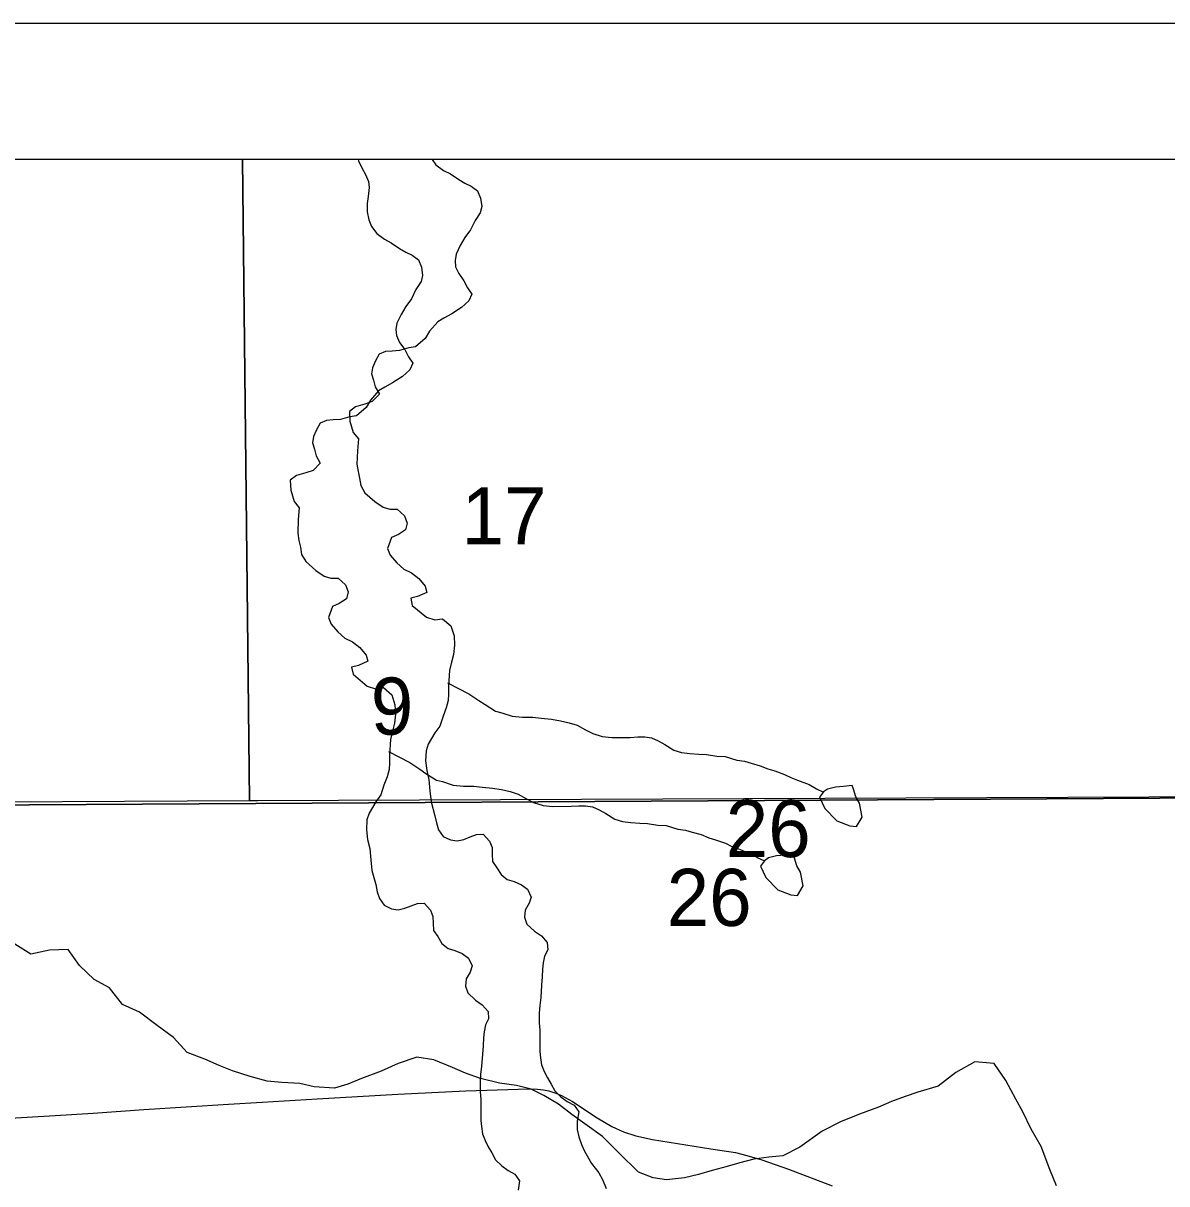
# Model space of a CAD drawing. Extents: x -21.1 to 50.3, y -4.9 to 22.1.
# Drawn here: x 6.727 to 7.565, y 20.149 to 21 of the extents above; entities that cross this region are included whole.
import ezdxf

# ---------------------------------------------------------------- set-up
doc = ezdxf.new("R2010")
doc.units = 0
for name, color, linetype in [('GM_X_Corporation', 7, 'Continuous'), ('GM_X_County', 7, 'Continuous'), ('GM_X_County_Road', 7, 'Continuous'), ('GM_X_Minor_Lake', 7, 'Continuous'), ('GM_X_Minor_River', 7, 'Continuous'), ('GM_X_Rail_Line_Text', 7, 'Continuous'), ('GM_X_Section_Text', 7, 'Continuous'), ('SH_Cut_Line', 7, 'Continuous'), ('SH_Data', 7, 'Continuous')]:
    doc.layers.add(name, color=color, linetype=linetype)

msp = doc.modelspace()

# ---------------------------------------------------------------- linework, layer by layer
at = {"layer": 'GM_X_Corporation'}
for points in [[(6.88768, 20.9), (5.88454, 20.9), (5.88596, 20.42484), (6.89298, 20.43015)], [(7.89976, 20.9), (6.88768, 20.9), (6.89298, 20.43015), (6.89867, 20.4302), (7.90835, 20.43439)]]:
    msp.add_lwpolyline(points, close=True, dxfattribs=at)
at = {"layer": 'GM_X_County'}
msp.add_lwpolyline([(8.9, 14.74638), (8.9, 20.9), (2.1, 20.9), (2.1, 14.1), (8.89319, 14.1)], dxfattribs=at)
at = {"layer": 'GM_X_County_Road'}
msp.add_lwpolyline([(6.71328, 20.19721), (6.75049, 20.19936), (6.77842, 20.20108), (6.81549, 20.2037), (6.87744, 20.20754), (6.90225, 20.20909), (6.94258, 20.21152), (7.00151, 20.21506), (7.0514, 20.21753), (7.0898, 20.21864), (7.10178, 20.21885), (7.10828, 20.21807), (7.1123, 20.2174), (7.11656, 20.21605), (7.12154, 20.21391), (7.12962, 20.20959), (7.14767, 20.19755), (7.15842, 20.19122), (7.16701, 20.18741), (7.17595, 20.18451), (7.18816, 20.18184), (7.2311, 20.17491), (7.24911, 20.17212), (7.25739, 20.1701), (7.26825, 20.16674), (7.28795, 20.15994), (7.3199, 20.14786)], dxfattribs=at)
at = {"layer": 'GM_X_Minor_Lake'}
for points in [[(7.31066, 20.43258), (7.31455, 20.42427), (7.32337, 20.41526), (7.3329, 20.41157), (7.33783, 20.41124), (7.34192, 20.41811), (7.33991, 20.42834), (7.33721, 20.43286), (7.33563, 20.43854), (7.33446, 20.44118)], [(7.33446, 20.44118), (7.32829, 20.44059), (7.32247, 20.44012), (7.31655, 20.43862), (7.31364, 20.43665), (7.31066, 20.43258)], [(7.26737, 20.38206), (7.27126, 20.37375), (7.28008, 20.36474), (7.28961, 20.36105), (7.29454, 20.36072), (7.29863, 20.3676), (7.29663, 20.37782), (7.29392, 20.38235), (7.29234, 20.38802), (7.29117, 20.39066)], [(7.29117, 20.39066), (7.285, 20.39007), (7.27918, 20.38961), (7.27326, 20.38811), (7.27035, 20.38613), (7.26737, 20.38206)]]:
    msp.add_lwpolyline(points, dxfattribs=at)
at = {"layer": 'GM_X_Minor_River'}
for points in [[(6.97254, 20.9), (6.9729, 20.89924), (6.97521, 20.89393), (6.97791, 20.88901), (6.98022, 20.88408), (6.98062, 20.87952), (6.9799, 20.87306), (6.97917, 20.86774), (6.9792, 20.86166), (6.98037, 20.85597), (6.9823, 20.85104), (6.98614, 20.84574), (6.99187, 20.8416), (6.99684, 20.83897), (7.00295, 20.83482), (7.00753, 20.83218), (7.01211, 20.82993), (7.0167, 20.82654), (7.01902, 20.82123), (7.01981, 20.81516)], [(7.02672, 20.9), (7.02943, 20.89626), (7.03516, 20.89211), (7.04012, 20.88948), (7.04624, 20.88534), (7.05082, 20.8827), (7.0554, 20.88045), (7.05999, 20.87705), (7.0623, 20.87175), (7.0631, 20.86567)], [(7.0631, 20.86567), (7.06198, 20.86111), (7.05821, 20.85539), (7.05482, 20.84853), (7.05066, 20.84281), (7.04727, 20.83709), (7.04426, 20.83062), (7.04352, 20.82605), (7.04393, 20.8215), (7.04624, 20.81657), (7.05008, 20.81127), (7.05277, 20.80597), (7.05584, 20.80143), (7.05359, 20.79648), (7.04829, 20.79151), (7.04108, 20.78691), (7.03539, 20.78384), (7.03083, 20.78116), (7.02478, 20.77429), (7.02176, 20.76895), (7.01457, 20.76283), (7.00962, 20.76204), (7.00278, 20.76011), (6.99745, 20.7597), (6.99251, 20.75929), (6.98795, 20.75737), (6.98531, 20.75241), (6.98306, 20.74746), (6.98232, 20.7429), (6.98387, 20.73835), (6.98504, 20.73341), (6.98811, 20.72811), (6.98281, 20.72277), (6.97749, 20.72084), (6.97065, 20.7189), (6.96611, 20.71545), (6.96653, 20.70824), (6.96886, 20.69989), (6.97269, 20.69536), (6.97198, 20.68662), (6.97165, 20.67674), (6.97244, 20.67142), (6.97361, 20.66649), (6.9744, 20.66117), (6.97748, 20.65588), (6.98474, 20.64946), (6.99086, 20.64531), (6.99582, 20.64382), (7.00115, 20.64385), (7.0065, 20.63894), (7.00843, 20.63363), (7.00732, 20.62869), (7.00201, 20.62524), (6.99708, 20.62293), (6.99407, 20.61494), (6.99601, 20.61001), (7.00098, 20.60434), (7.00596, 20.59981), (7.01168, 20.59718), (7.01704, 20.59303), (7.02164, 20.58736), (7.0228, 20.5828), (7.01597, 20.57973), (7.01103, 20.57856), (7.0122, 20.57325), (7.02252, 20.56457), (7.02863, 20.5627), (7.03433, 20.56349), (7.04045, 20.55821), (7.04278, 20.551), (7.04319, 20.54417), (7.04247, 20.53733), (7.04098, 20.53162), (7.03949, 20.52553), (7.03879, 20.51413), (7.03883, 20.50843), (7.03847, 20.50349), (7.03698, 20.49816), (7.03473, 20.49207), (7.03249, 20.48484), (7.02871, 20.47988), (7.0238, 20.4715), (7.02231, 20.46655), (7.02197, 20.45933), (7.02277, 20.45212), (7.02433, 20.44567), (7.02514, 20.43731), (7.02594, 20.42934), (7.02866, 20.4191), (7.02984, 20.41379), (7.03139, 20.40886), (7.03484, 20.40394), (7.04018, 20.40131), (7.04514, 20.40057), (7.05008, 20.40174), (7.05464, 20.40367), (7.0592, 20.40521), (7.06414, 20.40562), (7.06874, 20.40033), (7.07067, 20.39578), (7.0707, 20.39084)], [(7.01981, 20.81516), (7.01869, 20.81059), (7.01492, 20.80487), (7.01153, 20.79802), (7.00738, 20.79229), (7.00398, 20.78658), (7.00097, 20.7801), (7.00024, 20.77554), (7.00064, 20.77098), (7.00295, 20.76606), (7.00679, 20.76076), (7.00948, 20.75546), (7.01256, 20.75092), (7.0103, 20.74596), (7.005, 20.741), (6.99779, 20.7364), (6.9921, 20.73332), (6.98754, 20.73064), (6.98149, 20.72377), (6.97848, 20.71843), (6.97128, 20.71232), (6.96633, 20.71153), (6.95949, 20.70959), (6.95417, 20.70918), (6.94922, 20.70878), (6.94466, 20.70685), (6.94202, 20.7019), (6.93977, 20.69694), (6.93903, 20.69238), (6.94058, 20.68783), (6.94175, 20.6829), (6.94482, 20.6776), (6.93952, 20.67225), (6.9342, 20.67032), (6.92737, 20.66838), (6.92282, 20.66494), (6.92324, 20.65772), (6.92557, 20.64938), (6.9294, 20.64484), (6.92869, 20.6361), (6.92836, 20.62622), (6.92915, 20.6209), (6.93032, 20.61597), (6.93111, 20.61066), (6.93419, 20.60536), (6.94145, 20.59894), (6.94757, 20.59479), (6.95253, 20.5933), (6.95786, 20.59333), (6.96321, 20.58842), (6.96515, 20.58312), (6.96403, 20.57817), (6.95872, 20.57472), (6.95379, 20.57242), (6.95078, 20.56442), (6.95272, 20.55949), (6.9577, 20.55382), (6.96267, 20.54929), (6.96839, 20.54666), (6.97375, 20.54251), (6.97835, 20.53684), (6.97951, 20.53229), (6.97268, 20.52921), (6.96774, 20.52804), (6.96891, 20.52273), (6.97924, 20.51405), (6.98534, 20.51219), (6.99104, 20.51298), (6.99716, 20.50769), (6.99949, 20.50049), (6.99991, 20.49365), (6.99918, 20.48681), (6.99769, 20.4811), (6.9962, 20.47501), (6.9955, 20.46361), (6.99554, 20.45792), (6.99518, 20.45298), (6.99369, 20.44765), (6.99144, 20.44156), (6.9892, 20.43433), (6.98542, 20.42937), (6.98052, 20.42098), (6.97902, 20.41604), (6.97868, 20.40882), (6.97948, 20.4016), (6.98104, 20.39515), (6.98185, 20.3868), (6.98266, 20.37883), (6.98538, 20.36858), (6.98655, 20.36327), (6.9881, 20.35834), (6.99155, 20.35342), (6.9969, 20.35079), (7.00185, 20.35006), (7.00679, 20.35123), (7.01135, 20.35315), (7.01591, 20.3547), (7.02085, 20.3551), (7.02545, 20.34981), (7.02738, 20.34526), (7.02741, 20.34032)], [(7.03799, 20.5166), (7.05367, 20.50852), (7.06093, 20.50362), (7.06552, 20.5006), (7.07315, 20.4957), (7.07773, 20.49459), (7.08536, 20.49198), (7.09298, 20.49126), (7.10059, 20.4913), (7.10668, 20.49057), (7.1143, 20.48985), (7.12078, 20.48875), (7.12726, 20.48727), (7.13298, 20.4854), (7.13909, 20.48201), (7.14443, 20.47938), (7.1513, 20.47714), (7.15853, 20.47642), (7.17186, 20.4765), (7.17756, 20.47691), (7.18251, 20.47694), (7.18747, 20.4762), (7.19243, 20.47395), (7.19739, 20.47132), (7.20388, 20.46718), (7.20961, 20.46531), (7.2157, 20.46458), (7.22217, 20.46424), (7.22788, 20.46389), (7.2355, 20.46279), (7.2416, 20.46245), (7.24998, 20.45983), (7.2557, 20.4591), (7.26066, 20.45761), (7.26714, 20.45575), (7.27286, 20.4535), (7.27782, 20.45201), (7.28507, 20.44939), (7.28965, 20.44714), (7.29461, 20.44526), (7.303, 20.44189), (7.30834, 20.43888), (7.3135, 20.43645)], [(6.9947, 20.46609), (7.01038, 20.458), (7.01764, 20.4531), (7.02223, 20.45009), (7.02987, 20.44519), (7.03444, 20.44407), (7.04207, 20.44146), (7.04969, 20.44074), (7.0573, 20.44078), (7.06339, 20.44006), (7.07101, 20.43934), (7.07749, 20.43823), (7.08397, 20.43675), (7.08969, 20.43488), (7.0958, 20.4315), (7.10114, 20.42887), (7.10801, 20.42663), (7.11524, 20.42591), (7.12857, 20.42598), (7.13427, 20.42639), (7.13922, 20.42642), (7.14418, 20.42569), (7.14914, 20.42343), (7.1541, 20.4208), (7.1606, 20.41666), (7.16632, 20.41479), (7.17241, 20.41407), (7.17888, 20.41372), (7.1846, 20.41337), (7.19221, 20.41228), (7.19831, 20.41193), (7.2067, 20.40932), (7.21241, 20.40859), (7.21737, 20.4071), (7.22385, 20.40523), (7.22957, 20.40299), (7.23453, 20.40149), (7.24178, 20.39887), (7.24636, 20.39662), (7.25132, 20.39475), (7.25971, 20.39138), (7.26506, 20.38837), (7.27021, 20.38594)], [(7.0707, 20.39084), (7.07111, 20.38552), (7.07418, 20.38098), (7.07725, 20.37606), (7.08184, 20.37229), (7.08679, 20.37079), (7.09214, 20.36854), (7.09672, 20.36515), (7.09942, 20.35947), (7.09792, 20.3549), (7.09491, 20.34994), (7.09455, 20.34462), (7.0961, 20.33969), (7.10184, 20.33441), (7.10681, 20.33102), (7.11103, 20.3261), (7.11144, 20.32078), (7.10918, 20.31621), (7.10806, 20.31127), (7.10771, 20.30671), (7.10736, 20.30101), (7.10701, 20.29492), (7.1063, 20.2858), (7.10557, 20.2801), (7.10522, 20.2744), (7.10526, 20.26718), (7.10567, 20.26187), (7.10576, 20.24629), (7.10617, 20.24173), (7.10696, 20.23642), (7.10889, 20.23149), (7.1112, 20.22695), (7.11389, 20.2224), (7.11658, 20.21748), (7.12117, 20.21295), (7.12576, 20.20955), (7.13072, 20.20692), (7.13418, 20.202), (7.13307, 20.19516), (7.13311, 20.18908), (7.13428, 20.18377), (7.13622, 20.17808), (7.13853, 20.17315), (7.14352, 20.16406), (7.14889, 20.15725), (7.15158, 20.15233), (7.15429, 20.14589)], [(7.02741, 20.34032), (7.02782, 20.33501), (7.03089, 20.33047), (7.03396, 20.32554), (7.03855, 20.32177), (7.04351, 20.32028), (7.04885, 20.31803), (7.05344, 20.31463), (7.05613, 20.30895), (7.05463, 20.30438), (7.05162, 20.29943), (7.05127, 20.29411), (7.05281, 20.28918), (7.05856, 20.28389), (7.06352, 20.2805), (7.06774, 20.27558), (7.06815, 20.27027), (7.06589, 20.2657), (7.06477, 20.26075), (7.06442, 20.25619), (7.06407, 20.25049), (7.06372, 20.24441), (7.06302, 20.23529), (7.06228, 20.22959), (7.06193, 20.22389), (7.06198, 20.21667), (7.06238, 20.21135), (7.06247, 20.19578), (7.06288, 20.19122), (7.06367, 20.1859), (7.0656, 20.18098), (7.06791, 20.17643), (7.0706, 20.17189), (7.07329, 20.16696), (7.07788, 20.16243), (7.08247, 20.15904), (7.08744, 20.1564), (7.09089, 20.15149), (7.08978, 20.14464)], [(7.48434, 20.1477), (7.47942, 20.15984), (7.47298, 20.17653), (7.46579, 20.18942), (7.45973, 20.20194), (7.45443, 20.21142), (7.44723, 20.22507), (7.43852, 20.23758), (7.4245, 20.23872), (7.41047, 20.23076), (7.39757, 20.22089), (7.38279, 20.21634), (7.37331, 20.2133), (7.36345, 20.20951), (7.35397, 20.20534), (7.33994, 20.2004), (7.32592, 20.19471), (7.31265, 20.18789), (7.29634, 20.17613), (7.28383, 20.16968), (7.27359, 20.16892), (7.2626, 20.1674), (7.25236, 20.16474), (7.24288, 20.16209), (7.23189, 20.15905), (7.22203, 20.15602), (7.21179, 20.15374), (7.19853, 20.15222), (7.18867, 20.15374), (7.17806, 20.15791), (7.16366, 20.17194), (7.15154, 20.18407), (7.13866, 20.19318), (7.12918, 20.2), (7.11933, 20.20758), (7.10872, 20.21403), (7.09925, 20.21858), (7.08864, 20.22123), (7.07613, 20.22313), (7.0621, 20.22654), (7.05111, 20.23033), (7.04164, 20.2345), (7.028, 20.24019), (7.01549, 20.24208), (7.00184, 20.23753), (6.98933, 20.23184), (6.97492, 20.22653), (6.96506, 20.22236), (6.9552, 20.21932), (6.94042, 20.22046), (6.92981, 20.22273), (6.91654, 20.22349), (6.90593, 20.22463), (6.89342, 20.22804), (6.88053, 20.23221), (6.87068, 20.236), (6.86007, 20.24055), (6.84718, 20.24548), (6.83733, 20.25647), (6.8252, 20.2652), (6.81232, 20.27506), (6.79982, 20.28074), (6.79035, 20.29288), (6.77898, 20.29894), (6.76837, 20.30918), (6.76004, 20.32094), (6.74639, 20.32056), (6.73274, 20.31752), (6.7191, 20.32624)]]:
    msp.add_lwpolyline(points, dxfattribs=at)
at = {"layer": 'GM_X_Rail_Line_Text'}
for points in [[(8.9, 20.9), (2.80139, 20.9)], [(5.88332, 20.42279), (6.48301, 20.42563), (7.60161, 20.43214)], [(7.60161, 20.43214), (6.48301, 20.42563), (5.88332, 20.42279)]]:
    msp.add_lwpolyline(points, dxfattribs=at)
at = {"layer": 'SH_Cut_Line'}
msp.add_lwpolyline([(8.9, 16.40522), (8.9, 20.9), (2.1, 20.9)], dxfattribs=at)
at = {"layer": 'SH_Data'}
msp.add_line((2, 21), (9, 21), dxfattribs=at)

# ---------------------------------------------------------------- texts
at = {"layer": 'GM_X_Section_Text'}
for s, height, p in [('17', 0.041856, (7.04836, 20.618)), ('9', 0.04186, (6.98178, 20.47848)), ('26', 0.041856, (7.24193, 20.38879)), ('26', 0.041856, (7.19864, 20.33828))]:
    msp.add_text(s, height=height, rotation=0.00001, dxfattribs=at).set_placement(p)

doc.saveas('drawing.dxf')
